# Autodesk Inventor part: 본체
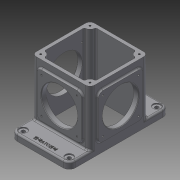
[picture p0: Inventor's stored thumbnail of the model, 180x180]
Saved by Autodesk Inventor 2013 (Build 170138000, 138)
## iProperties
Created: 2018-09
Part Number: 본체
Material: 일반
Document SubType Name: Modeling
Designer: mduedu
Density: 2.71 g/cm^3
Mass: 972.977 g
Surface Area: 957.184 cm^2
Volume: 359.032 cm^3
Author: mduedu
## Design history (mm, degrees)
sketch "스케치1"
  geometry: L1 (90, 52.5)-(-90, 52.5); L2 (-90, 52.5)-(-90, -52.5); L3 (-90, -52.5)-(90, -52.5); L4 (90, -52.5)-(90, 52.5); L5 (90, 52.5)-(-90, -52.5); L6 (-90, 52.5)-(90, -52.5); 1 further point
  constraints: 12 end point, 2 midpoint, 2 parallel, 1 horizontal, 1 perpendicular
  dimensions: "d0" = 180 distance of L3.end L2.end; "d1" = 105 distance of L2.end L1.end
extrude "돌출1" new body sketch "스케치1" distance "d2" = 12; taper "d3" = 0 deg
sketch "스케치2"
  geometry: L1 (-52.5, -52.5)-(52.5, -52.5); L2 (52.5, -52.5)-(52.5, 52.5); L3 (52.5, 52.5)-(-52.5, 52.5); L4 (-52.5, 52.5)-(-52.5, -52.5); L5 (-52.5, -52.5)-(52.5, 52.5); L6 (52.5, -52.5)-(-52.5, 52.5); 1 further point
  constraints: 12 end point, 2 midpoint, 2 parallel, 1 horizontal, 1 perpendicular
  dimensions: "d4" = 105 distance of L3.end L2.end; "d5" = 105 distance of L2.end L1.end
extrude "돌출2" join sketch "스케치2" distance "d6" = 100; taper "d7" = 0 deg
sketch "스케치14"
  geometry: L1 (-52.5, 52.5)-(52.5, 52.5) reference; L2 (52.5, 52.5)-(52.5, -52.5) reference; L3 (52.5, -52.5)-(-52.5, -52.5) reference; L4 (-52.5, -52.5)-(-52.5, 52.5) reference; L5 (46.5, 46.5)-(-46.5, 46.5); L6 (-46.5, 46.5)-(-46.5, -46.5); L7 (-46.5, -46.5)-(46.5, -46.5); L8 (46.5, -46.5)-(46.5, 46.5); 1 further point
  constraints: 8 end point, 3 other
  dimensions: "d85" = 6 distance between parallel lines of L5 L1
extrude "돌출10" cut sketch "스케치14" stored distance "d86" = 10; taper "d87" = 0 deg
fillet "모깎기1" dims "d12" = 8
sketch "스케치15"
  geometry: A1 r 8 centre (-44.5, 44.5) between (-44.5, 52.5) and (-52.5, 44.5) reference; A2 r 8 centre (44.5, 44.5) between (52.5, 44.5) and (44.5, 52.5) reference; A3 r 8 centre (44.5, -44.5) between (44.5, -52.5) and (52.5, -44.5) reference; A4 r 8 centre (-44.5, -44.5) between (-52.5, -44.5) and (-44.5, -52.5) reference; 5 further points
  constraints: 4 coincident, 4 vertical alignment, 8 other
extrude "돌출11" join sketch "스케치15" stored distance "d88" = 10; taper "d89" = 0 deg
fillet "모깎기15" dims "d90" = 3
sketch "스케치6"
  geometry: L1 (50, 19)-(130, 19); L2 (130, 19)-(130, 99); L3 (130, 99)-(50, 99); L4 (50, 99)-(50, 19); L5 (50, 19)-(130, 99); L6 (130, 19)-(50, 99); L7 (0, 0)-(180, 0) reference; 4 further points
  constraints: 12 end point, 4 midpoint, 2 parallel, 1 horizontal, 1 perpendicular, 1 vertical alignment
  dimensions: "d25" = 80 distance of L3.end L2.end; "d26" = 80 distance of L2.end L1.end; "d27" = 59 distance of point (90, 0) point (90, 59)
extrude "돌출6" join sketch "스케치6" distance "d28" = 3; taper "d29" = 0 deg
fillet "모깎기7" dims "d30" = 8
sketch "스케치7"
  geometry: C1 r 32.5 at (90, 59); 1 further point
  constraints: 1 centre point, 1 vertical alignment
  dimensions: "d32" = 65 diameter of C1; "d33" = 59 distance of C1.centre point (90, 0)
extrude "돌출7" cut sketch "스케치7" stored distance "d34" = 3; taper "d35" = 0 deg
fillet "모깎기9" dims "d36" = 3
sketch "스케치8"
  geometry: L1 (4.5, 7)-(84.5, 7); L2 (84.5, 7)-(84.5, 87); L3 (84.5, 87)-(4.5, 87); L4 (4.5, 87)-(4.5, 7); L5 (4.5, 7)-(84.5, 87); L6 (84.5, 7)-(4.5, 87); L7 (-8, -12)-(97, -12) reference; C1 r 32.5 at (44.5, 47); 4 further points
  constraints: 12 end point, 4 midpoint, 2 parallel, 1 centre point, 1 coincident, 1 horizontal, 1 perpendicular, 1 vertical alignment
  dimensions: "d37" = 80 distance of L3.end L2.end; "d38" = 80 distance of L2.end L1.end; "d39" = 59 distance from line of point (44.5, 47) L7; "d40" = 65 diameter of C1
extrude "돌출8" join sketch "스케치8" distance "d41" = 3; taper "d42" = 0 deg
fillet "모깎기10" dims "d43" = 8
extrude "돌출9" cut sketch "스케치8" stored distance "d44" = 3; taper "d45" = 0 deg
fillet "모깎기11" dims "d46" = 3
sketch "스케치9"
  geometry: L1 (50, 91)-(50, 27) reference; L2 (58, 19)-(122, 19) reference; L3 (130, 27)-(130, 91) reference; L4 (122, 99)-(58, 99) reference; C1 r 32.5 at (90, 59) reference; A1 r 8 centre (58, 91) between (58, 99) and (50, 91) reference; A2 r 8 centre (58, 27) between (50, 27) and (58, 19) reference; A3 r 8 centre (122, 27) between (122, 19) and (130, 27) reference; A4 r 8 centre (122, 91) between (130, 91) and (122, 99) reference; 5 further points
  constraints: 4 coincident
hole "구멍1" sketch "스케치9" at (58, 91), (122, 91), (122, 27), (58, 27) diameter "d47" = 3.242; stored, may be unused: countersink angle "d51" = 90 deg, drill point angle "d53" = 118 deg; dims "d48" = 6, "d49" = 4, "d50" = 2, "d52" = 9
sketch "스케치10"
  geometry: L1 (12.5, 7)-(76.5, 7) reference; L2 (84.5, 15)-(84.5, 79) reference; L3 (76.5, 87)-(12.5, 87) reference; L4 (4.5, 79)-(4.5, 15) reference; C1 r 32.5 at (44.5, 47) reference; A1 r 8 centre (12.5, 15) between (4.5, 15) and (12.5, 7) reference; A2 r 8 centre (76.5, 15) between (76.5, 7) and (84.5, 15) reference; A3 r 8 centre (76.5, 79) between (84.5, 79) and (76.5, 87) reference; A4 r 8 centre (12.5, 79) between (12.5, 87) and (4.5, 79) reference; 5 further points
  constraints: 4 coincident
hole "구멍2" sketch "스케치10" at (12.5, 79), (76.5, 79), (76.5, 15), (12.5, 15) diameter "d54" = 3.242; stored, may be unused: countersink angle "d58" = 90 deg, drill point angle "d60" = 118 deg; dims "d55" = 6, "d56" = 4, "d57" = 2, "d59" = 9
fillet "모깎기12" dims "d68" = 11
sketch "스케치16"
  geometry: A1 r 11 centre (-79, 41.5) between (-79, 52.5) and (-90, 41.5) reference; A2 r 11 centre (-79, -41.5) between (-90, -41.5) and (-79, -52.5) reference; A3 r 11 centre (79, 41.5) between (90, 41.5) and (79, 52.5) reference; A4 r 11 centre (79, -41.5) between (79, -52.5) and (90, -41.5) reference; 5 further points
  constraints: 4 coincident
hole "구멍5" sketch "스케치16" at (-79, 41.5), (79, 41.5), (79, -41.5), (-79, -41.5) diameter "d91" = 6.6; stored, may be unused: countersink angle "d95" = 90 deg, drill point angle "d97" = 118 deg; dims "d92" = 6, "d93" = 14, "d94" = 2, "d96" = 8
fillet "모깎기13" dims "d77" = 3
fillet "모깎기14" dims "d78" = 3
chamfer "모따기1" distance "d79" = 1; stored, may be unused: second distance "d80" = 2, angle "d81" = 45 deg
sketch "스케치17"
  geometry: A1 r 8 centre (-44.5, 44.5) between (-44.5, 52.5) and (-52.5, 44.5) reference; A2 r 8 centre (-44.5, -44.5) between (-52.5, -44.5) and (-44.5, -52.5) reference; A3 r 8 centre (44.5, -44.5) between (44.5, -52.5) and (52.5, -44.5) reference; A4 r 8 centre (44.5, 44.5) between (52.5, 44.5) and (44.5, 52.5) reference; 5 further points
  constraints: 4 coincident
hole "구멍6" sketch "스케치17" at (-44.5, 44.5), (44.5, 44.5), (44.5, -44.5), (-44.5, -44.5) diameter "d98" = 3.242; stored, may be unused: countersink angle "d102" = 90 deg, drill point angle "d104" = 118 deg; dims "d99" = 8, "d100" = 15, "d101" = 2, "d103" = 10
sketch "스케치13"
  geometry: L1 (90, -41.5)-(90, 41.5) reference; 2 further points
  constraints: 1 horizontal alignment, 1 other
  dimensions: "d82" = 10 distance from line of point (80, 0) L1
feature "엠보싱1" sketch "스케치13" dims "d0" = 180, "d1" = 105, "d25" = 80, "d26" = 80, "d27" = 59, "d83" = 0.5, "d84" = 0
node "솔리드1"
mirror "대칭1"
mirror "대칭2"
node "투영된 루프2"
node "투영된 루프3"
node "투영된 루프6"
